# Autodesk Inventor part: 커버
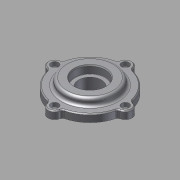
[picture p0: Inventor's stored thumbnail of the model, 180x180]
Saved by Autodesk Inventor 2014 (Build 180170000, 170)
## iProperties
Company: 한국ATC센터
Created: 2015-12
Part Number: 커버
Document SubType Name: Modeling
Designer: mdu
Density: 1 g/cm^3
Material: 일반
Appearance: Default
Author: mdu
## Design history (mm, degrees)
sketch "스케치1"
  geometry: C1 r 1.621 at (0, 6.75) reference; C2 r 1.621 at (-37, -30.25) reference; C3 r 1.621 at (0, -67.25) reference; C4 r 1.621 at (37, -30.25) reference; C5 r 10 at (0, -30.25) reference; C6 r 12 at (0, -30.25); C7 r 24.5 at (0, -30.25) reference; A1 r 3 centre (-38.77, -20.408) between (-38.239, -23.361) and (-35.862, -21.146) reference; A2 r 7 centre (-37, -30.25) between (-38.239, -23.361) and (-38.239, -37.139) reference; A3 r 3 centre (-38.77, -40.092) between (-35.862, -39.354) and (-38.239, -37.139) reference; A4 r 37 centre (0, -30.25) between (-35.862, -39.354) and (-9.104, -66.113) reference; A5 r 3 centre (-9.842, -69.02) between (-6.889, -68.489) and (-9.104, -66.113) reference; A6 r 7 centre (0, -67.25) between (-6.889, -68.489) and (6.889, -68.489) reference; A7 r 3 centre (9.842, -69.02) between (9.104, -66.112) and (6.889, -68.489) reference; A8 r 37 centre (0, -30.25) between (9.104, -66.112) and (35.863, -39.354) reference; A9 r 3 centre (38.77, -40.092) between (38.239, -37.139) and (35.863, -39.354) reference; A10 r 7 centre (37, -30.25) between (38.239, -37.139) and (38.239, -23.361) reference; A11 r 3 centre (38.77, -20.408) between (35.863, -21.146) and (38.239, -23.361) reference; A12 r 37 centre (0, -30.25) between (35.863, -21.146) and (9.104, 5.612) reference; A13 r 3 centre (9.842, 8.52) between (6.889, 7.989) and (9.104, 5.612) reference; A14 r 7 centre (0, 6.75) between (6.889, 7.989) and (-6.889, 7.989) reference; A15 r 3 centre (-9.842, 8.52) between (-9.104, 5.612) and (-6.889, 7.989) reference; A16 r 37 centre (0, -30.25) between (-9.104, 5.612) and (-35.862, -21.146) reference; 1 further point
  constraints: 1 centre point, 1 coincident
  dimensions: "d2" = 2 radial gap between concentric circles of C6 C5
extrude "돌출1" new body sketch "스케치1" distance "d0" = 8; taper "d1" = 0 deg
sketch "스케치2"
  geometry: C1 r 23.5 at (0, -30.25) reference; C2 r 12 at (0, -30.25) reference; 1 further point
extrude "돌출2" join sketch "스케치2" distance "d4" = 5; taper "d5" = 0 deg
sketch "스케치3"
  geometry: C1 r 23.5 at (0, 0) reference; C2 r 20.5 at (0, 0); 1 further point
  constraints: 1 centre point
  dimensions: "d6" = 3 radial gap between concentric circles of C2 C1
node "작업 평면1"
extrude "돌출3" join sketch "스케치3" stored distance "d7" = 5; taper "d8" = 0 deg
fillet "모깎기1" dims "d9" = 3
sketch "스케치4"
  geometry: C1 r 12 at (0, -30.25) reference; C2 r 27 at (0, -30.25); 1 further point
  constraints: 1 centre point
  dimensions: "d10" = 15 radial gap between concentric circles of C1 C2
extrude "돌출4" join sketch "스케치4" distance "d11" = 7; taper "d12" = 0 deg
fillet "모깎기2" dims "d13" = 3
chamfer "모따기1" distance "d14" = 1; stored, may be unused: second distance "d15" = 2, angle "d16" = 45 deg
node "작업점1"
  node "작업축1"
chamfer "모따기2" distance "d24" = 1; stored, may be unused: second distance "d25" = 2, angle "d26" = 45 deg
hole "구멍6" diameter "d43" = 4.5; stored, may be unused: countersink angle "d47" = 90 deg, drill point angle "d49" = 118 deg; dims "d41" = 10, "d42" = 10, "d44" = 6, "d45" = 8, "d46" = 4.4, "d48" = 8
sketch "스케치8"
  geometry: C1 r 12 at (0, 0) reference; C2 r 16 at (0, 0); 1 further point
  constraints: 1 centre point, 1 coincident
  dimensions: "d53" = 32 diameter of C2
extrude "돌출5" cut sketch "스케치8" distance "d54" = 8.3; taper "d55" = 0 deg
fillet "모깎기3" dims "d56" = 0.3
chamfer "모따기3" distance "d57" = 1.2; stored, may be unused: second distance "d58" = 2, angle "d59" = 30 deg
node "솔리드1"
pattern_circular "원형 패턴1" dims angle "d51" = 360 deg
node "참조1"
node "참조2"
